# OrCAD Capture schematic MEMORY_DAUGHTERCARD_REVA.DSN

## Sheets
1 001_TITLE: title: Memory Daughter Card; rev: X1; company: NXP Semiconductors; note: SCH-xxxxx PDF: SPF-xxxxx; note: 6501 William Cannon Drive West; note: Austin, TX 78735-8598
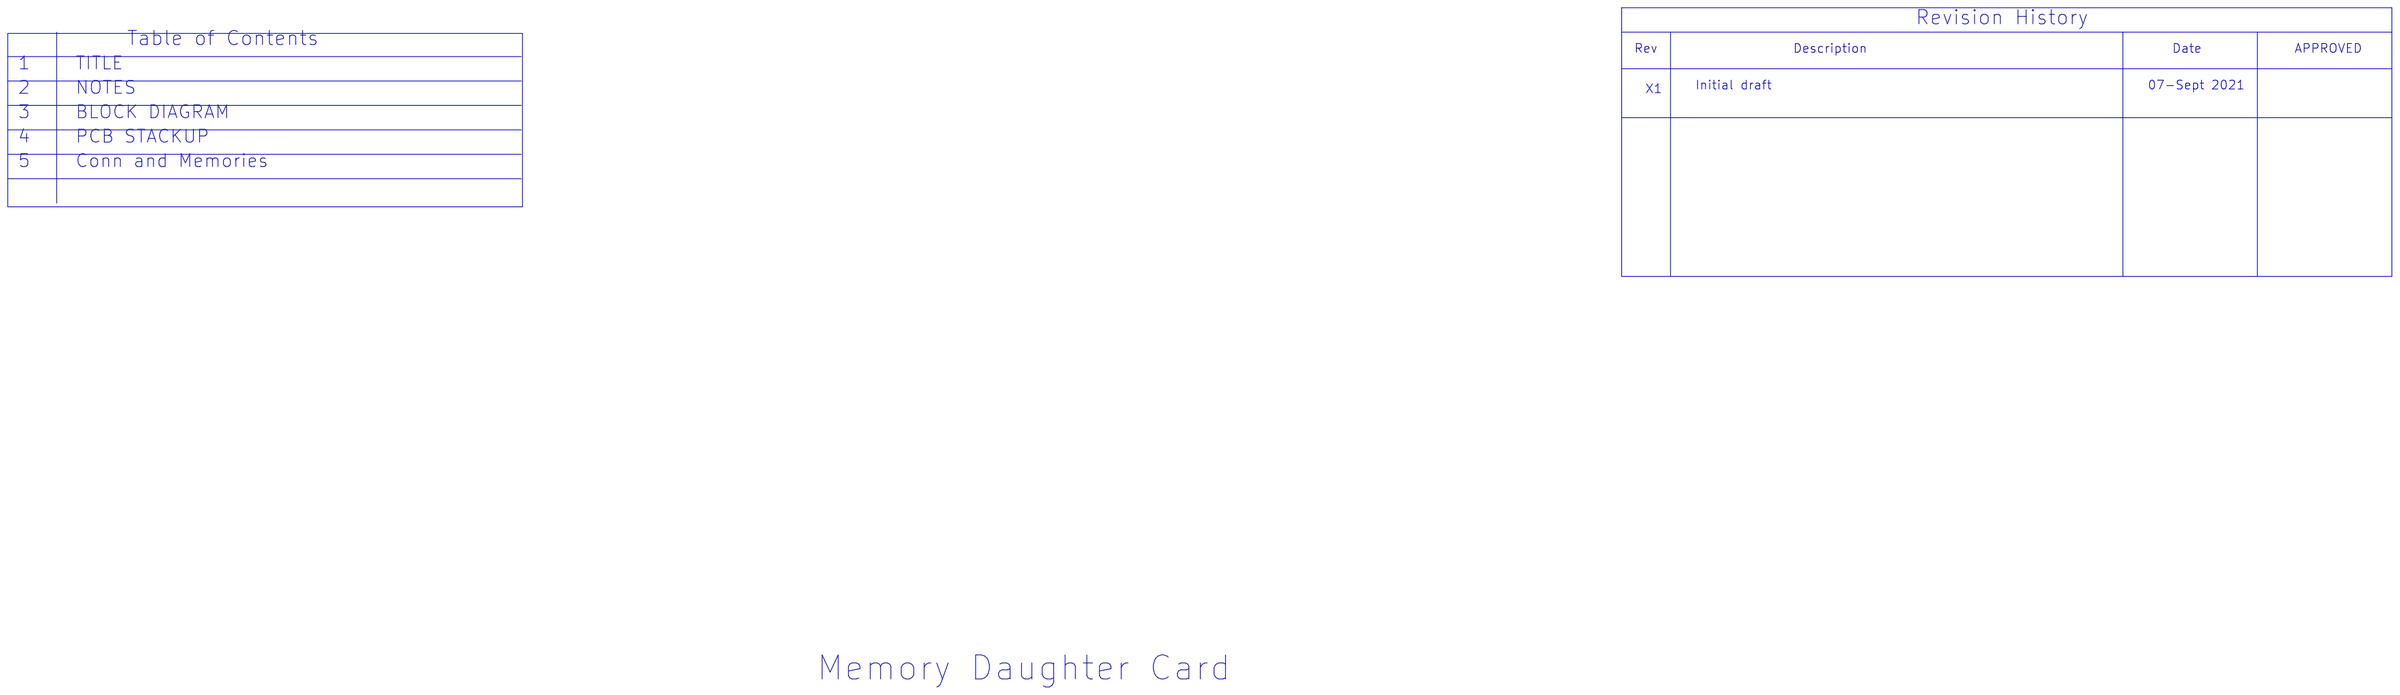
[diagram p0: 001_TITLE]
2 002_NOTES
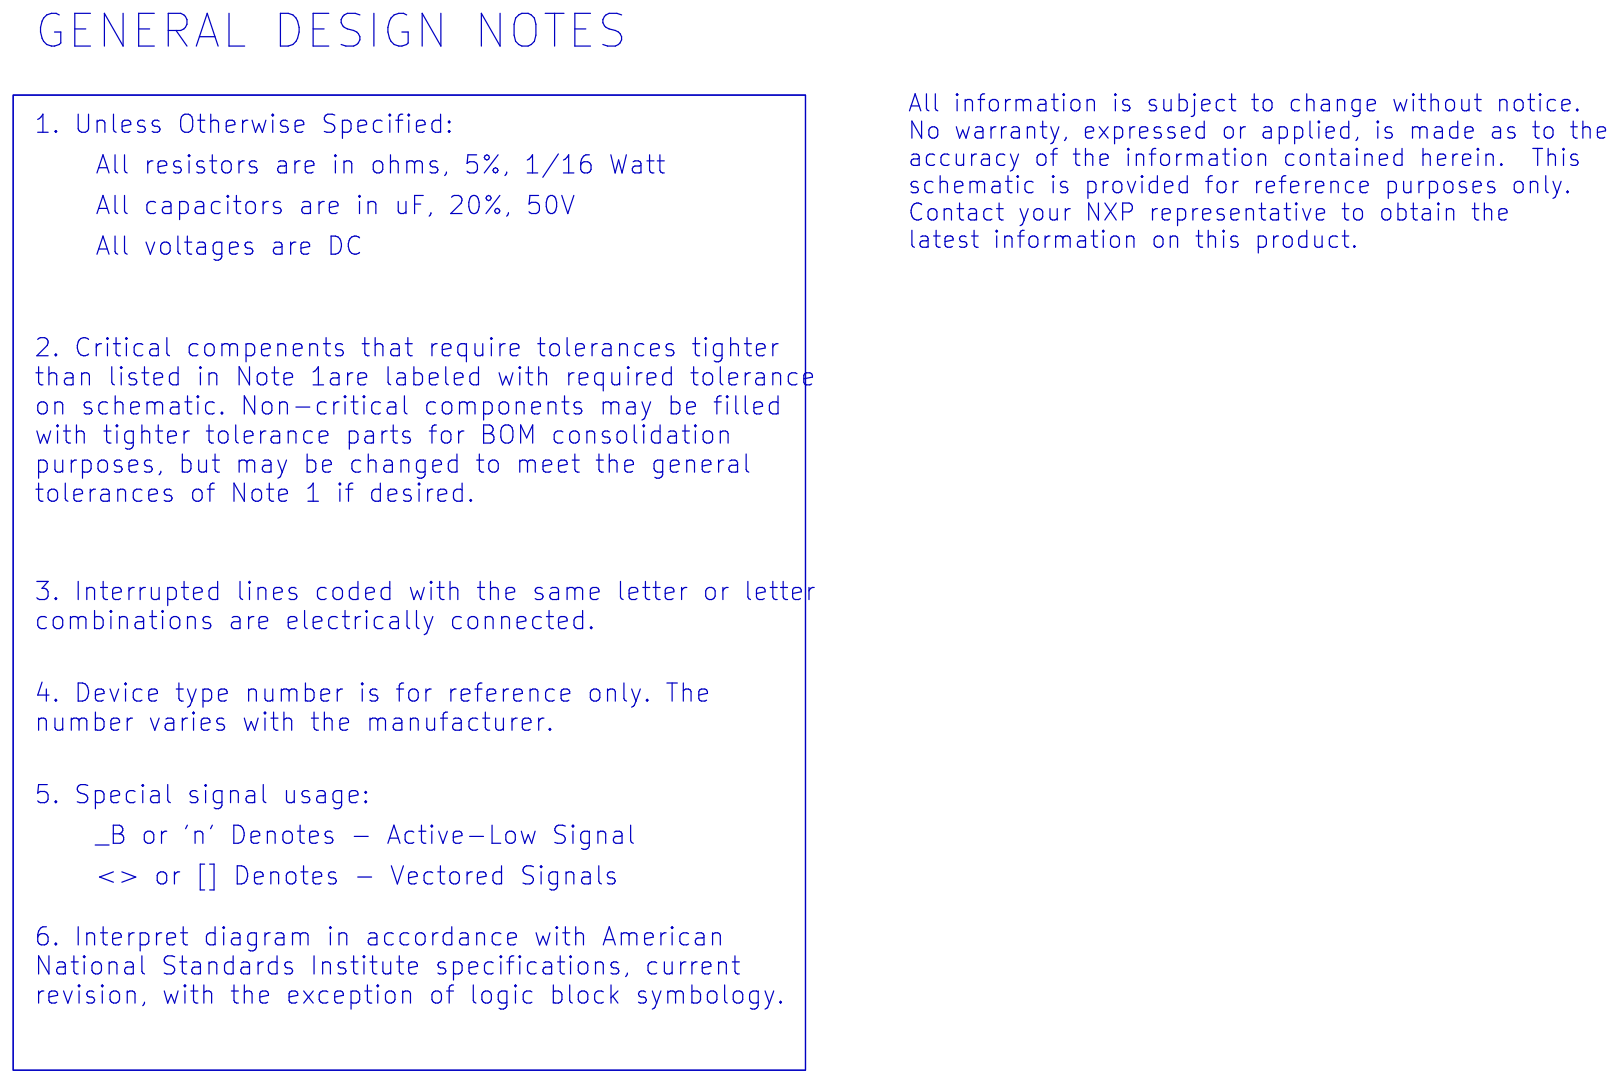
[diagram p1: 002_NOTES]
3 003_BLOCK DIAGRAM
4 004_PCB STACKUP
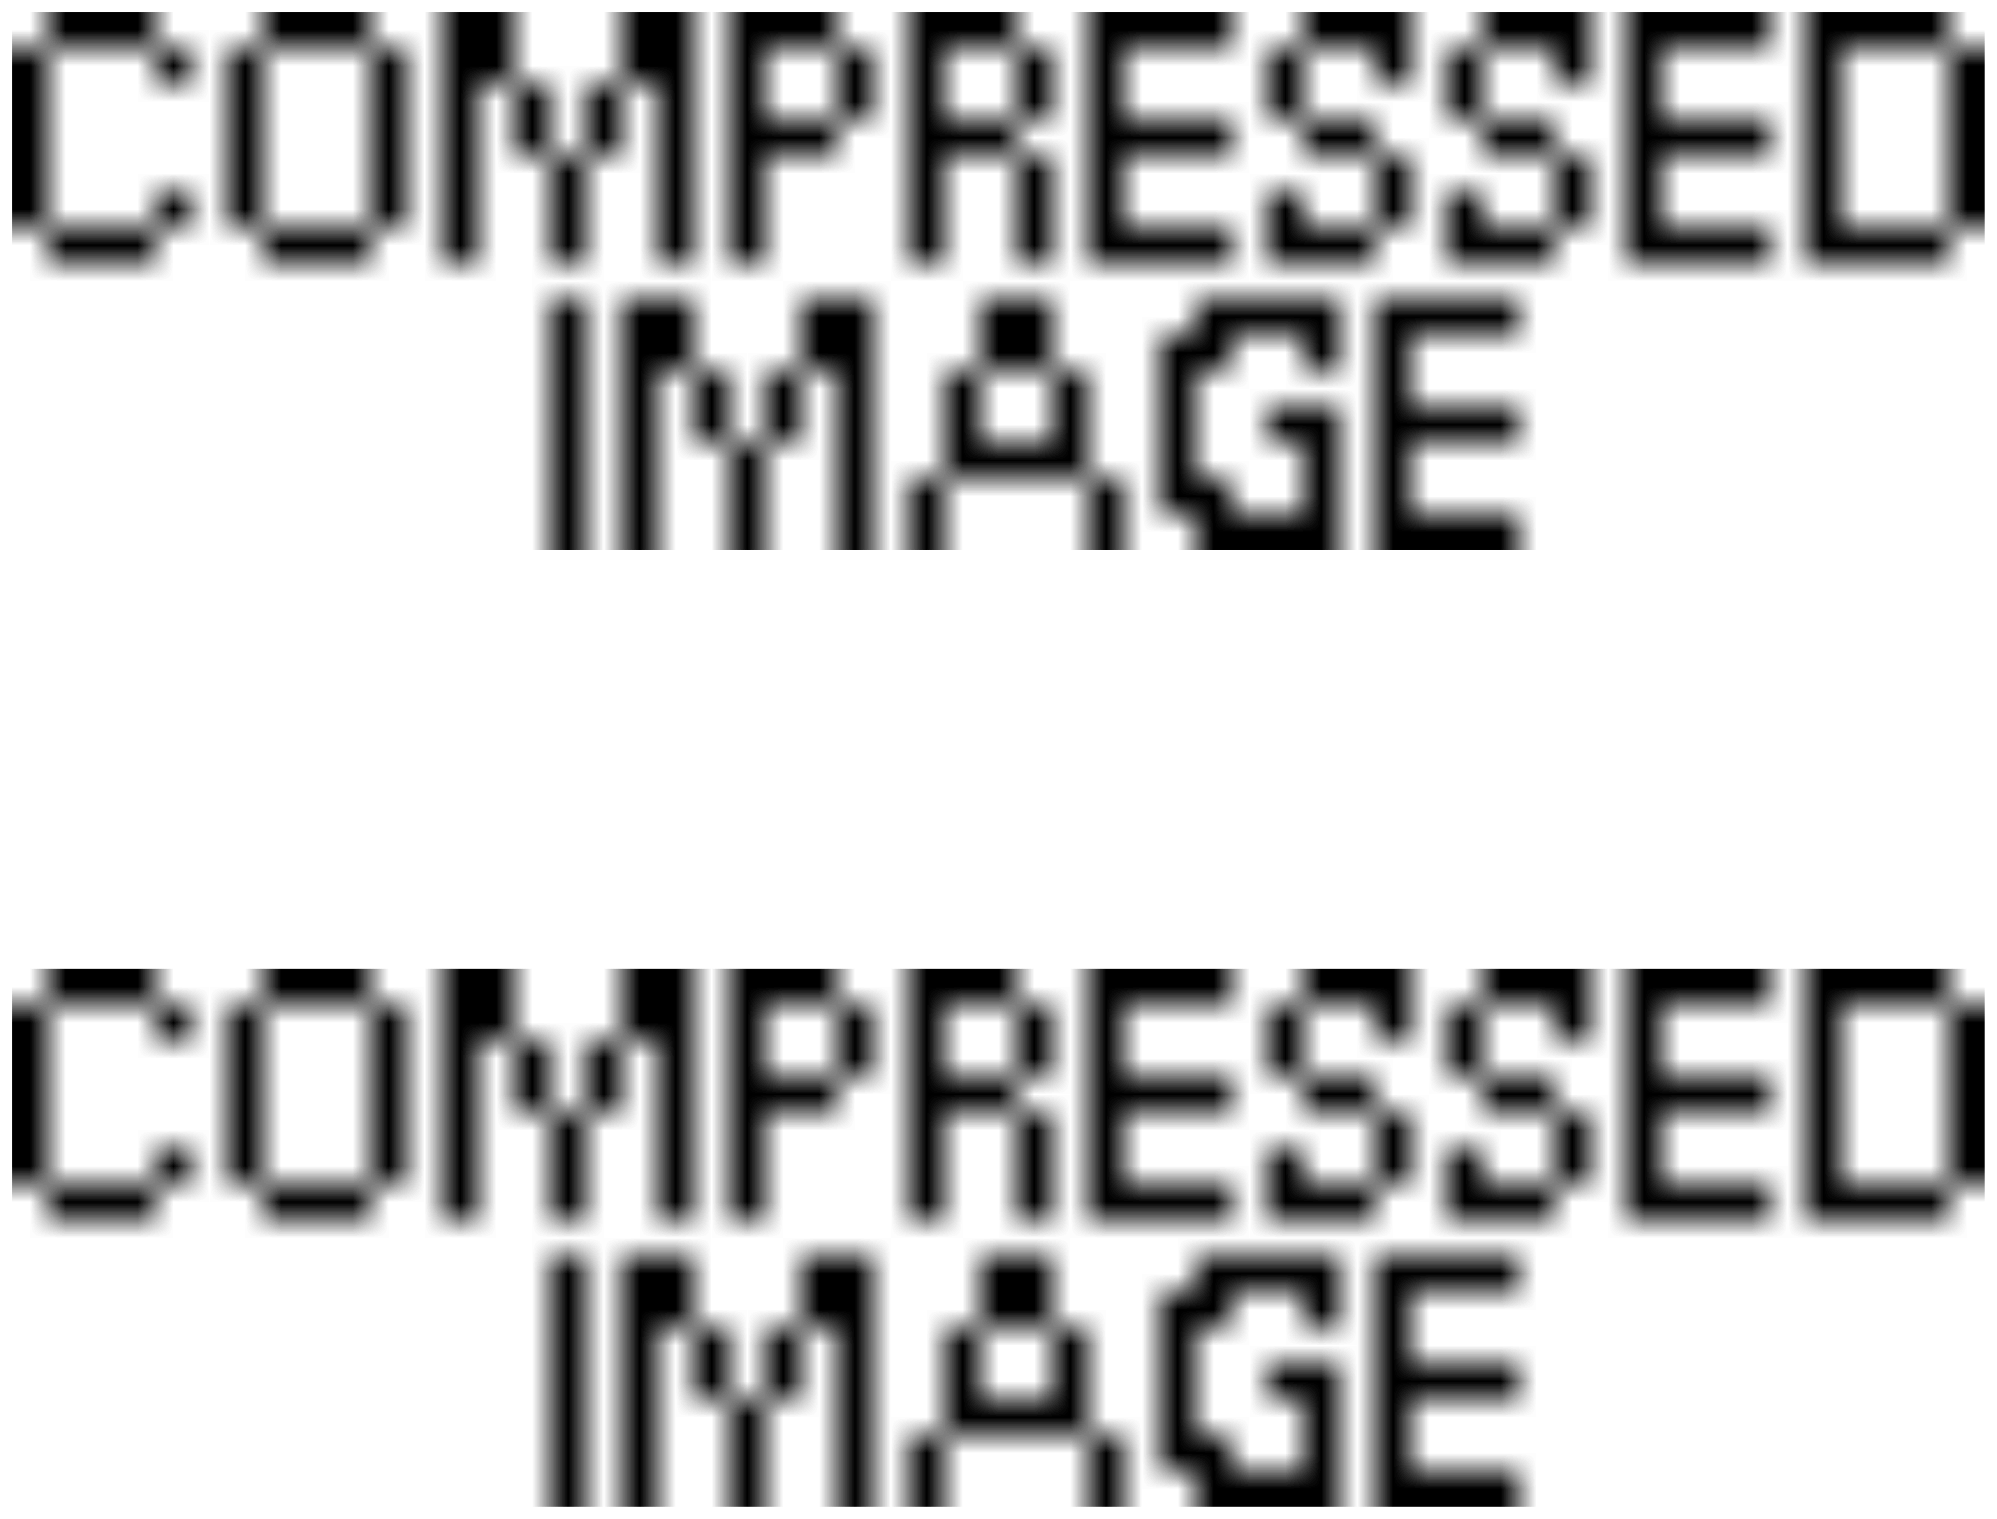
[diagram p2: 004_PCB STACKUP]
5 005_Connections: size E
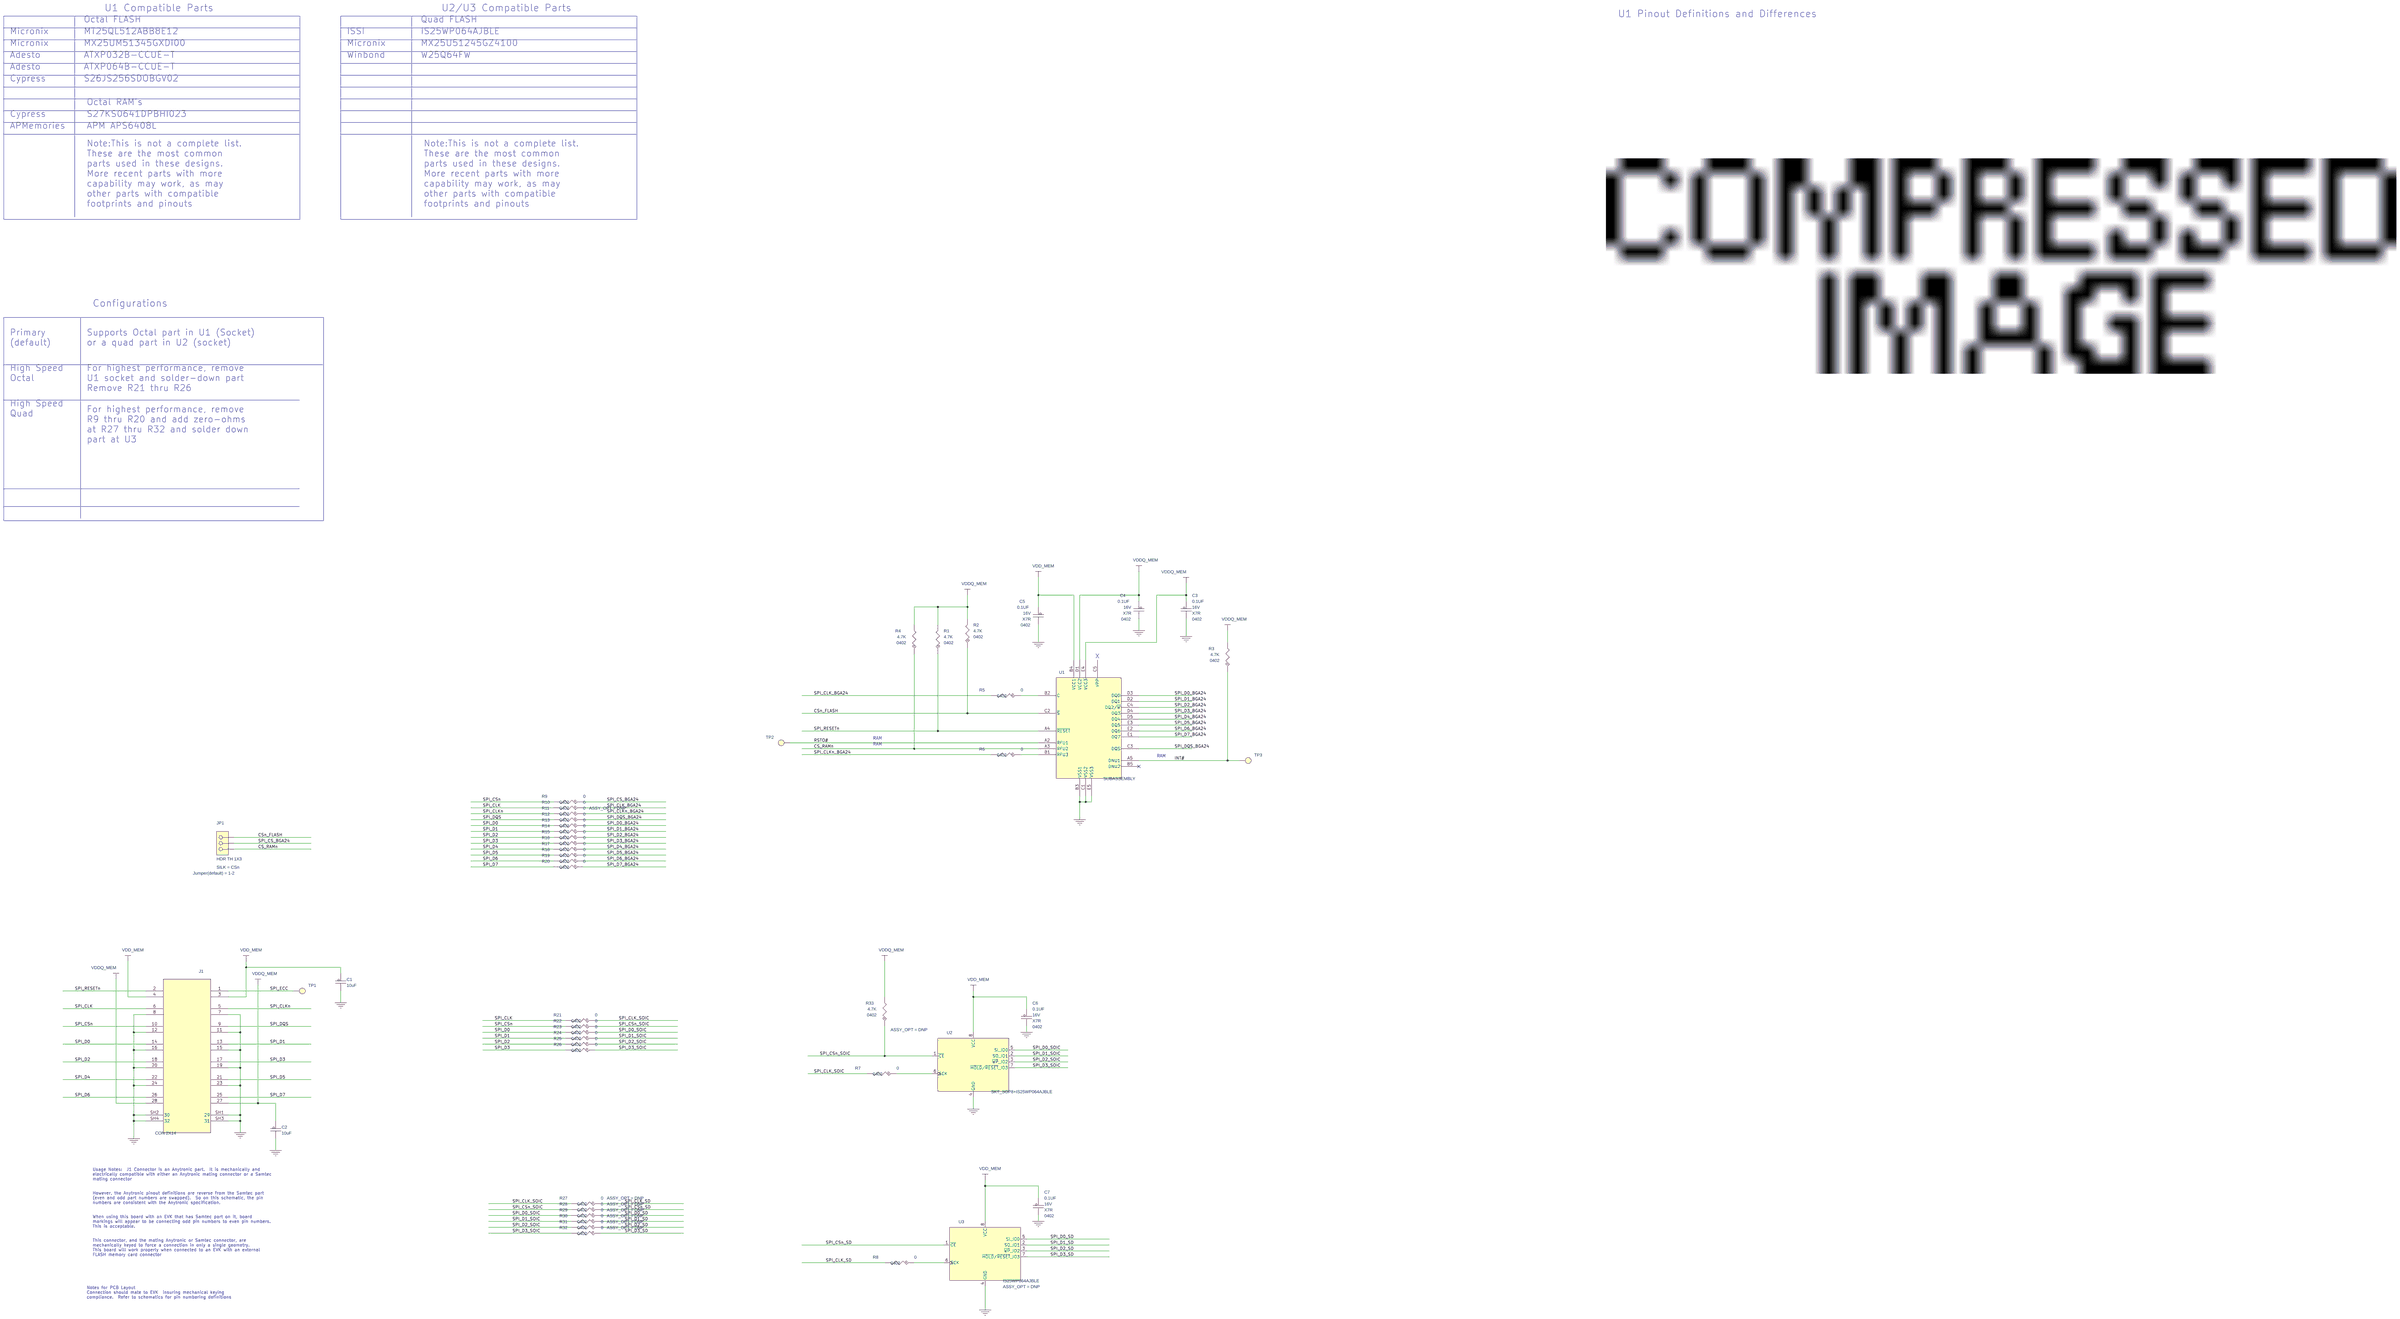
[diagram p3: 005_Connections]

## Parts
C1  10uF  [cc0402_tol0p2]
C2  10uF  [cc0402_tol0p2]
C3  0.1UF  [CC0402_25]
C4  0.1UF  [CC0402_25]
C5  0.1UF  [CC0402_25]
C6  0.1UF  [CC0402_25]
C7  0.1UF  [CC0402_25]
J1  CON 2X14  [con_28m_0p8_smt]
JP1  HDR TH 1X3  [HDR103]
R1  4.7K  [RC0402_25]
R2  4.7K  [RC0402_25]
R3  4.7K  [RC0402_25]
R4  4.7K  [RC0402_25]
R5  0  [RC0402_25]
R6  0  [RC0402_25]
R7  0  [RC0402_25]
R8  0  [RC0402_25]
R9  0  [RC0402_25]
R10  0  [RC0402_25]
R11  0  [RC0402_25]
R12  0  [RC0402_25]
R13  0  [RC0402_25]
R14  0  [RC0402_25]
R15  0  [RC0402_25]
R16  0  [RC0402_25]
R17  0  [RC0402_25]
R18  0  [RC0402_25]
R19  0  [RC0402_25]
R20  0  [RC0402_25]
R21  0  [RC0402_25]
R22  0  [RC0402_25]
R23  0  [RC0402_25]
R24  0  [RC0402_25]
R25  0  [RC0402_25]
R26  0  [RC0402_25]
R27  0  [RC0402_25]
R28  0  [RC0402_25]
R29  0  [RC0402_25]
R30  0  [RC0402_25]
R31  0  [RC0402_25]
R32  0  [RC0402_25]
R33  4.7K  [RC0402_25]
TP1  TPAD_050  [TPAD_050]
TP2  TPAD_050  [TPAD_050]
TP3  TPAD_050  [TPAD_050]
U1  SUBASSEMBLY  [skt_bga24_1mm_25x25mm]
U2  SKT_SOP8+IS25WP064AJBLE  [skt8_sop_1p27_th]
U3  IS25WP064AJBLE  [SO8-25X75-200]

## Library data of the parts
C1 C2 = CAP_NP: CAP CER 10uF 10V 20% X5R 0402_WIDE; AGILE_PN: 150-79255; CAD_APPROVED: Yes; FPLIST: CC0402_25,CC0402_HD,0402_CC; HEIGHT: 0.7MM; MFG_NAME01: NIC COMPONENTS CORP; MFG_PN01: NMC0402X5R106M10TRPF; ROHS: Yes; Tolerance: 20%; VOLTAGE: 10V
C3-C7 = CAP_NP: CAP CER 0.1UF 16V 10% X7R 0402; AGILE_PN: 150-75182; CAD_APPROVED: Yes; FPLIST: CC0402_25,CC0402_HD,0402_CC,CAPC0402_L; HEIGHT: 0.635MM; MFG_NAME01: AVX; MFG_PN01: 0402YC104KAT2A; Pkg: 0402; ROHS: Yes; Spec: 16V; Temp Range: -55°C to +125°C; Tolerance: 10%; Type: X7R; VOLTAGE: 16V
J1 = QSE_014_DP: CON 2X14 PLUG SHRD SMT 0.8MM SP 171H AU; AGILE_PN: 211-81615; CAD_APPROVED: Yes; HEIGHT: 4.34MM; MFG_NAME01: ANYTRONIC CORPORATION LIMITED; MFG_PN01: 4608050M3 2805R-20LF-28; Package Type: Surface Mount; ROHS: Yes; Temp Range: -20°C to 105°C
JP1 = CONN_HDR_3X1: HDR 1X3 TH 100MIL SP 339H AU 100L; AGILE_PN: 210-75726; CAD_APPROVED: Yes; HEIGHT: 8.65MM; Jumper(default): 1-2; MFG_NAME01: SAMTEC; MFG_PN01: TSW-103-07-G-S; Package Size: 7.62 x 2.54 mm; ROHS: Yes; SILK: CSn; Temp Range: -55°C to +125°C
R1-R4 = RES: RES MF 4.7K OHM 1/16W 1% 0402; AGILE_PN: 470-80911; CAD_APPROVED: Yes; FPLIST: RC0402_25,RC0402_HD,0402_CC; HEIGHT: 0.4MM; MFG_NAME01: YAGEO; MFG_PN01: RC0402FR-074K7L; Pkg: 0402; ROHS: Yes; Tolerance: 1%
R5-R10 R12-R26 = RES: RES MF ZERO OHM 1/16W -- AEC-Q200 0402; AGILE_PN: 470-81849; CAD_APPROVED: Yes; FPLIST: RC0402_25,RC0402_HD,0402_CC; HEIGHT: 0.45 MM; MFG_NAME01: STACKPOLE ELECTRONICS; MFG_PN01: RMCF0402ZT0R00; Pkg: 0402; ROHS: Yes; Special: DNS
R11 R27-R32 = RES: RES MF ZERO OHM 1/16W -- AEC-Q200 0402; AGILE_PN: 470-81849; ASSY_OPT: DNP; CAD_APPROVED: Yes; FPLIST: RC0402_25,RC0402_HD,0402_CC; HEIGHT: 0.45 MM; MFG_NAME01: STACKPOLE ELECTRONICS; MFG_PN01: RMCF0402ZT0R00; Pkg: 0402; ROHS: Yes; Special: DNS
R33 = RES: RES MF 4.7K OHM 1/16W 1% 0402; AGILE_PN: 470-80911; ASSY_OPT: DNP; CAD_APPROVED: Yes; FPLIST: RC0402_25,RC0402_HD,0402_CC; HEIGHT: 0.4MM; MFG_NAME01: YAGEO; MFG_PN01: RC0402FR-074K7L; Pkg: 0402; ROHS: Yes; Tolerance: 1%
TP1-TP3 = TEST_POINT_L: TEST POINT PAD 50MIL DIA SMT, NO PART TO ORDER; AGILE_PN: 211-76644; CAD_APPROVED: Yes; HEIGHT: 0.1MM; MFG_NAME01: NOTACOMPONENT; MFG_PN01: NOTACOMPONENT; ROHS: Yes
U1 = MT35XU512ABA1G12: SUBASSEMBLY SKT 24 BGA SMT 1MM 1377H + IC MEM FLASH SERIAL NOR 2GB OCTAL DDR SPI 1.7-2.0V T-PBGA24; AGILE_PN: 750-77861; CAD_APPROVED: Yes; HEIGHT: 1.2MM; MFG_NAME01: ENPLAS; MFG_PN01: 211-79856,342-00727; ROHS: Yes
U2 = 25WP_8P: SUBASSEMBLY SKT 8 SOP TH 1.27MM 575H AU 126L + IC MEM FLASH QPI 64Mb 1.65-1.95V SOIC8W; AGILE_PN: 750-78235; CAD_APPROVED: Yes; HEIGHT: 14.6MM; MFG_NAME01: SUBASSEMBLY; MFG_PN01: 210-79761+334-77734; ROHS: Yes
U3 = 25WP_8P: IC MEM FLASH QPI 64Mb 1.65-1.95V SOIC8W; AGILE_PN: 334-77734; ASSY_OPT: DNP; CAD_APPROVED: Yes; HEIGHT: 2.16MM; MFG_NAME01: ISSI; MFG_PN01: IS25WP064A-JBLE; ROHS: Yes; Temp Range: -40C to +105C; VOLTAGE: 1.65-1.95V

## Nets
GND: C1.2 C2.2 C3.2 C4.2 C5.2 C6.2 C7.2 J1.7 J1.8 J1.11 J1.12 J1.15 J1.16 J1.19 J1.20 J1.23 J1.24 J1.SH1(29) J1.SH2(30) J1.SH3(31) J1.SH4(32) U1.B3(VSS1) U1.C1(VSS2) U1.E5(VSS3) U2.4(GND) U3.4(GND)
VDD_MEM: C1.1 C5.1 C6.1 C7.1 J1.3 J1.4 U1.B4(VCC1) U2.8(VCC) U3.8(VCC)
VDDQ_MEM: C2.1 C3.1 C4.1 J1.27 J1.28 R1.2 R2.2 R3.2 R4.2 R33.2 U1.D1(VCC2) U1.E4(VCC3)
CS_RAMn: JP1.3 R4.1 U1.A3(RFU2)
CSn_FLASH: JP1.1 R2.1 U1.C2(~{S})
INT#: R3.1 TP3.1(TP) U1.A5(DNU1)
RSTO#: TP2.1(TP) U1.A2(RFU1)
SPI_CLK: J1.6 R10.2 R21.2
SPI_CLK_BGA24: R5.2 R10.1
SPI_CLK_SD: R8.2 R27.1
SPI_CLK_SOIC: R7.2 R21.1 R27.2
SPI_CLKn: J1.5 R11.2
SPI_CLKn_BGA24: R6.2 R11.1
SPI_CS_BGA24: JP1.2 R9.1
SPI_CSn: J1.10 R9.2 R22.2
SPI_CSn_SD: R28.1 U3.1(~{CE})
SPI_CSn_SOIC: R22.1 R28.2 R33.1 U2.1(~{CE})
SPI_D0: J1.14 R13.2 R23.2
SPI_D0_BGA24: R13.1 U1.D3(DQ0)
SPI_D0_SD: R29.1 U3.5(SI_IO0)
SPI_D0_SOIC: R23.1 R29.2 U2.5(SI_IO0)
SPI_D1: J1.13 R14.2 R24.2
SPI_D1_BGA24: R14.1 U1.D2(DQ1)
SPI_D1_SD: R30.1 U3.2(SO_IO1)
SPI_D1_SOIC: R24.1 R30.2 U2.2(SO_IO1)
SPI_D2: J1.18 R15.2 R25.2
SPI_D2_BGA24: R15.1 U1.C4(DQ2/~{W})
SPI_D2_SD: R31.1 U3.3(~{WP}_IO2)
SPI_D2_SOIC: R25.1 R31.2 U2.3(~{WP}_IO2)
SPI_D3: J1.17 R16.2 R26.2
SPI_D3_BGA24: R16.1 U1.D4(DQ3)
SPI_D3_SD: R32.1 U3.7(~{HOLD}/~{RESET}_IO3)
SPI_D3_SOIC: R26.1 R32.2 U2.7(~{HOLD}/~{RESET}_IO3)
SPI_D4: J1.22 R17.2
SPI_D4_BGA24: R17.1 U1.D5(DQ4)
SPI_D5: J1.21 R18.2
SPI_D5_BGA24: R18.1 U1.E3(DQ5)
SPI_D6: J1.26 R19.2
SPI_D6_BGA24: R19.1 U1.E2(DQ6)
SPI_D7: J1.25 R20.2
SPI_D7_BGA24: R20.1 U1.E1(DQ7)
SPI_DQS: J1.9 R12.2
SPI_DQS_BGA24: R12.1 U1.C3(DQS)
SPI_ECC: J1.1 TP1.1(TP)
SPI_RESETn: J1.2 R1.1 U1.A4(~{RESET})
VPP: U1.C5(VPP)
N50940399: R6.1 U1.B1(RFU3)
N50940402: R5.1 U1.B2(C)
N50947464: R7.1 U2.6(SCK)
N50953647: R8.1 U3.6(SCK)

Not connected (* = marked no-connect by the designer): U1 B5(DNU2)*

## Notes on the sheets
sheet 1
- Revision History
- Table of Contents
- 1
- TITLE
- Rev
- Description
- Date
- APPROVED
- 2
- NOTES
- X1
- Initial draft
- 07-Sept 2021
- 3
- BLOCK DIAGRAM
- 4
- PCB STACKUP
- 5
- Conn and Memories
- Memory Daughter Card
sheet 2
- GENERAL DESIGN NOTES
- All information is subject to change without notice.
  No warranty, expressed or applied, is made as to the
  accuracy of the information contained herein.  This
  schematic is provided for reference purposes only.
  Contact your NXP representative to obtain the
  latest information on this product.
- 1. Unless Otherwise Specified:
- All resistors are in ohms, 5%, 1/16 Watt
- All capacitors are in uF, 20%, 50V
- All voltages are DC
- 2. Critical compenents that require tolerances tighter
  than listed in Note 1are labeled with required tolerance
  on schematic. Non-critical components may be filled
  with tighter tolerance parts for BOM consolidation
  purposes, but may be changed to meet the general
  tolerances of Note 1 if desired.
- 3. Interrupted lines coded with the same letter or letter
  combinations are electrically connected.
- 4. Device type number is for reference only. The
  number varies with the manufacturer.
- 5. Special signal usage:
- _B or 'n' Denotes - Active-Low Signal
- <> or [] Denotes - Vectored Signals
- 6. Interpret diagram in accordance with American
  National Standards Institute specifications, current
  revision, with the exception of logic block symbology.
sheet 5
- U1 Compatible Parts
- U2/U3 Compatible Parts
- U1 Pinout Definitions and Differences
- Octal FLASH
- Quad FLASH
- Micronix
- MT25QL512ABB8E12
- ISSI
- IS25WP064AJBLE
- Micronix
- MX25UM51345GXDI00
- Micronix
- MX25U51245GZ4100
- Adesto
- ATXP032B-CCUE-T
- Winbond
- W25Q64FW
- Adesto
- ATXP064B-CCUE-T
- Cypress
- S26JS256SDOBGV02
- Octal RAM's
- Cypress
- S27KS0641DPBHI023
- APMemories
- APM APS6408L
- Note:This is not a complete list.
  These are the most common
  parts used in these designs.
  More recent parts with more
  capability may work, as may
  other parts with compatible
  footprints and pinouts
- Note:This is not a complete list.
  These are the most common
  parts used in these designs.
  More recent parts with more
  capability may work, as may
  other parts with compatible
  footprints and pinouts
- Configurations
- Primary
  (default)
- Supports Octal part in U1 (Socket)
  or a quad part in U2 (socket)
- High Speed
  Octal
- For highest performance, remove
  U1 socket and solder-down part
  Remove R21 thru R26
- High Speed
  Quad
- For highest performance, remove
  R9 thru R20 and add zero-ohms
  at R27 thru R32 and solder down
  part at U3
- X
- RAM
- RAM
- RAM
- Usage Notes:  J1 Connector is an Anytronic part.  It is mechanically and
  electrically compatible with either an Anytronic mating connector or a Samtec
  mating connector
- However, the Anytronic pinout definitions are reverse from the Samtec part
  (even and odd part numbers are swapped).  So on this schematic, the pin
  numbers are consistent with the Anytronic specification.
- When using this board with an EVK that has Samtec part on it, board
  markings will appear to be connecting odd pin numbers to even pin numbers.
  This is acceptable.
- This connector, and the mating Anytronic or Samtec connector, are
  mechanically keyed to force a connection in only a single geometry.
  This board will work properly when connected to an EVK with an external
  FLASH memory card connector
- Notes for PCB Layout
  Connection should mate to EVK  insuring mechanical keying
  compliance.  Refer to schematics for pin numbering definitions
